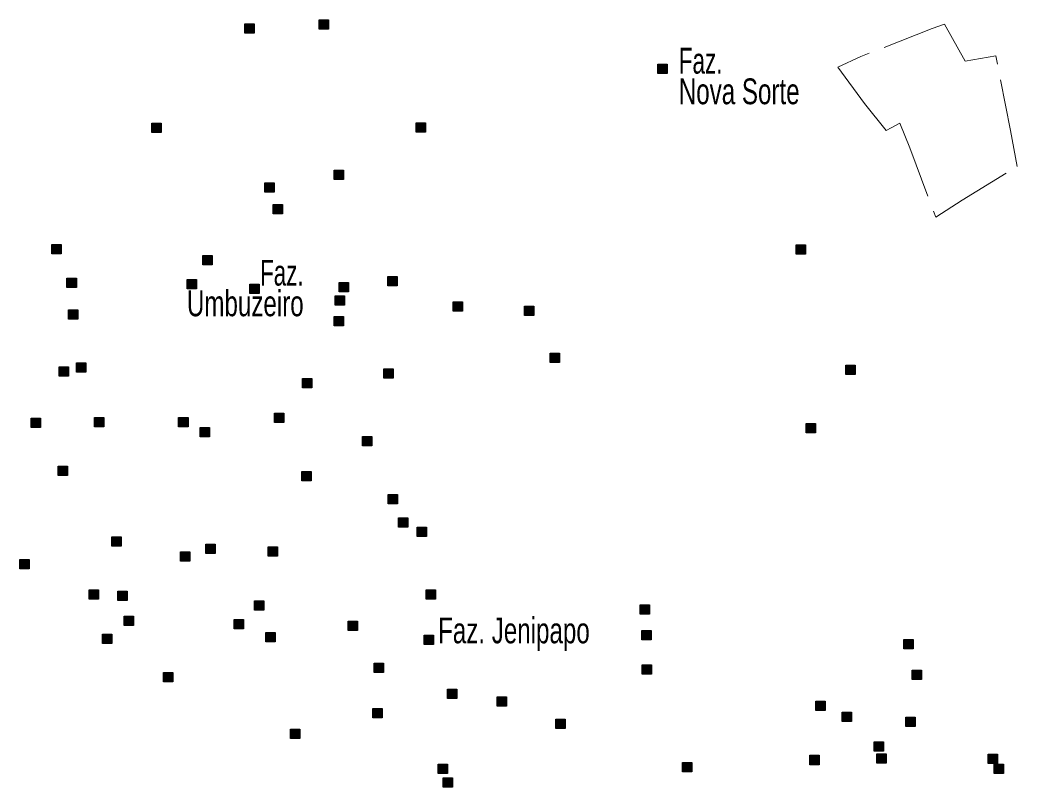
# Model space of a CAD drawing. Extents: x 445.6 to 500, y 8618.1 to 8673.4.
# Drawn here: x 463.55 to 469.73, y 8639.36 to 8644.12 of the extents above; entities that cross this region are included whole.
import ezdxf
from ezdxf.enums import TextEntityAlignment as Align

# ---------------------------------------------------------------- set-up
doc = ezdxf.new("R2010")
doc.units = 0
doc.header["$LTSCALE"] = 0.064
doc.linetypes.add('DOT_DASHED', pattern=[7.7, 5, -1.2, 0.3, -1.2])
doc.layers.add('2', color=7, linetype='Continuous', lineweight=25)
doc.layers.add('22', color=7, linetype='DOT_DASHED', lineweight=13)
doc.layers.add('61', color=7, linetype='Continuous')

msp = doc.modelspace()

# ---------------------------------------------------------------- hatches: boundary and pattern name
at = {"layer": '2'}
for points in [[(465.4002, 8644.1188), (465.4582, 8644.1188), (465.4582, 8644.0608), (465.4002, 8644.0608)], [(464.9408, 8644.0951), (464.9988, 8644.0951), (464.9988, 8644.0371), (464.9408, 8644.0371)], [(467.5005, 8643.8438), (467.5585, 8643.8438), (467.5585, 8643.7858), (467.5005, 8643.7858)], [(464.3621, 8643.4778), (464.4201, 8643.4778), (464.4201, 8643.4198), (464.3621, 8643.4198)], [(466.0028, 8643.4799), (466.0608, 8643.4799), (466.0608, 8643.4219), (466.0028, 8643.4219)], [(465.4937, 8643.1865), (465.5517, 8643.1865), (465.5517, 8643.1285), (465.4937, 8643.1285)], [(465.0647, 8643.1085), (465.1227, 8643.1085), (465.1227, 8643.0505), (465.0647, 8643.0505)], [(465.1154, 8642.973), (465.1734, 8642.973), (465.1734, 8642.915), (465.1154, 8642.915)], [(463.7423, 8642.7258), (463.8003, 8642.7258), (463.8003, 8642.6678), (463.7423, 8642.6678)], [(468.359, 8642.7224), (468.417, 8642.7224), (468.417, 8642.6644), (468.359, 8642.6644)], [(464.6796, 8642.658), (464.7376, 8642.658), (464.7376, 8642.6), (464.6796, 8642.6)], [(463.8369, 8642.5157), (463.8949, 8642.5157), (463.8949, 8642.4577), (463.8369, 8642.4577)], [(464.5817, 8642.5089), (464.6397, 8642.5089), (464.6397, 8642.4509), (464.5817, 8642.4509)], [(465.8266, 8642.5259), (465.8846, 8642.5259), (465.8846, 8642.4679), (465.8266, 8642.4679)], [(464.9701, 8642.4784), (465.0281, 8642.4784), (465.0281, 8642.4204), (464.9701, 8642.4204)], [(465.5241, 8642.4886), (465.5821, 8642.4886), (465.5821, 8642.4306), (465.5241, 8642.4306)], [(465.5004, 8642.4073), (465.5584, 8642.4073), (465.5584, 8642.3493), (465.5004, 8642.3493)], [(463.847, 8642.3192), (463.905, 8642.3192), (463.905, 8642.2612), (463.847, 8642.2612)], [(466.2319, 8642.3701), (466.2899, 8642.3701), (466.2899, 8642.3121), (466.2319, 8642.3121)], [(466.6741, 8642.3429), (466.7321, 8642.3429), (466.7321, 8642.2849), (466.6741, 8642.2849)], [(465.4937, 8642.2785), (465.5517, 8642.2785), (465.5517, 8642.2205), (465.4937, 8642.2205)], [(466.8332, 8642.0516), (466.8912, 8642.0516), (466.8912, 8641.9936), (466.8332, 8641.9936)], [(463.7889, 8641.9668), (463.8469, 8641.9668), (463.8469, 8641.9088), (463.7889, 8641.9088)], [(463.8949, 8641.9919), (463.9529, 8641.9919), (463.9529, 8641.9339), (463.8949, 8641.9339)], [(465.801, 8641.9533), (465.859, 8641.9533), (465.859, 8641.8953), (465.801, 8641.8953)], [(468.668, 8641.9775), (468.726, 8641.9775), (468.726, 8641.9195), (468.668, 8641.9195)], [(465.2966, 8641.8928), (465.3546, 8641.8928), (465.3546, 8641.8348), (465.2966, 8641.8348)], [(463.6155, 8641.648), (463.6735, 8641.648), (463.6735, 8641.59), (463.6155, 8641.59)], [(464.0079, 8641.6521), (464.0659, 8641.6521), (464.0659, 8641.5941), (464.0079, 8641.5941)], [(464.5295, 8641.6514), (464.5875, 8641.6514), (464.5875, 8641.5934), (464.5295, 8641.5934)], [(465.1243, 8641.6793), (465.1823, 8641.6793), (465.1823, 8641.6213), (465.1243, 8641.6213)], [(464.6627, 8641.5894), (464.7207, 8641.5894), (464.7207, 8641.5314), (464.6627, 8641.5314)], [(468.4214, 8641.615), (468.4794, 8641.615), (468.4794, 8641.557), (468.4214, 8641.557)], [(465.6702, 8641.5337), (465.7282, 8641.5337), (465.7282, 8641.4757), (465.6702, 8641.4757)], [(463.7812, 8641.3496), (463.8392, 8641.3496), (463.8392, 8641.2916), (463.7812, 8641.2916)], [(465.2932, 8641.3168), (465.3512, 8641.3168), (465.3512, 8641.2588), (465.2932, 8641.2588)], [(465.8288, 8641.1734), (465.8868, 8641.1734), (465.8868, 8641.1154), (465.8288, 8641.1154)], [(465.8931, 8641.0289), (465.9511, 8641.0289), (465.9511, 8640.9709), (465.8931, 8640.9709)], [(466.008, 8640.9713), (466.066, 8640.9713), (466.066, 8640.9133), (466.008, 8640.9133)], [(464.1144, 8640.9103), (464.1724, 8640.9103), (464.1724, 8640.8523), (464.1144, 8640.8523)], [(464.6987, 8640.8662), (464.7567, 8640.8662), (464.7567, 8640.8082), (464.6987, 8640.8082)], [(465.0838, 8640.8493), (465.1418, 8640.8493), (465.1418, 8640.7913), (465.0838, 8640.7913)], [(463.5451, 8640.7712), (463.6031, 8640.7712), (463.6031, 8640.7132), (463.5451, 8640.7132)], [(464.54, 8640.8188), (464.598, 8640.8188), (464.598, 8640.7608), (464.54, 8640.7608)], [(463.9741, 8640.5815), (464.0321, 8640.5815), (464.0321, 8640.5235), (463.9741, 8640.5235)], [(466.0654, 8640.5817), (466.1234, 8640.5817), (466.1234, 8640.5237), (466.0654, 8640.5237)], [(464.1515, 8640.5749), (464.2095, 8640.5749), (464.2095, 8640.5169), (464.1515, 8640.5169)], [(464.9993, 8640.5139), (465.0573, 8640.5139), (465.0573, 8640.4559), (464.9993, 8640.4559)], [(467.3912, 8640.4902), (467.4492, 8640.4902), (467.4492, 8640.4322), (467.3912, 8640.4322)], [(464.1921, 8640.419), (464.2501, 8640.419), (464.2501, 8640.361), (464.1921, 8640.361)], [(464.8744, 8640.3987), (464.9324, 8640.3987), (464.9324, 8640.3407), (464.8744, 8640.3407)], [(465.5803, 8640.3886), (465.6383, 8640.3886), (465.6383, 8640.3306), (465.5803, 8640.3306)], [(464.057, 8640.3072), (464.115, 8640.3072), (464.115, 8640.2492), (464.057, 8640.2492)], [(465.0703, 8640.3174), (465.1283, 8640.3174), (465.1283, 8640.2594), (465.0703, 8640.2594)], [(466.0519, 8640.3005), (466.1099, 8640.3005), (466.1099, 8640.2425), (466.0519, 8640.2425)], [(467.4014, 8640.331), (467.4594, 8640.331), (467.4594, 8640.273), (467.4014, 8640.273)], [(469.027, 8640.2735), (469.085, 8640.2735), (469.085, 8640.2155), (469.027, 8640.2155)], [(465.7411, 8640.1277), (465.7991, 8640.1277), (465.7991, 8640.0697), (465.7411, 8640.0697)], [(467.4047, 8640.1175), (467.4627, 8640.1175), (467.4627, 8640.0595), (467.4047, 8640.0595)], [(464.4353, 8640.0701), (464.4933, 8640.0701), (464.4933, 8640.0121), (464.4353, 8640.0121)], [(469.079, 8640.0846), (469.137, 8640.0846), (469.137, 8640.0266), (469.079, 8640.0266)], [(466.1967, 8639.9652), (466.2547, 8639.9652), (466.2547, 8639.9072), (466.1967, 8639.9072)], [(466.5041, 8639.9178), (466.5621, 8639.9178), (466.5621, 8639.8598), (466.5041, 8639.8598)], [(465.7339, 8639.8467), (465.7919, 8639.8467), (465.7919, 8639.7887), (465.7339, 8639.7887)], [(468.4818, 8639.8908), (468.5398, 8639.8908), (468.5398, 8639.8328), (468.4818, 8639.8328)], [(466.8688, 8639.7789), (466.9268, 8639.7789), (466.9268, 8639.7209), (466.8688, 8639.7209)], [(468.644, 8639.8231), (468.702, 8639.8231), (468.702, 8639.7651), (468.644, 8639.7651)], [(469.0403, 8639.7925), (469.0983, 8639.7925), (469.0983, 8639.7345), (469.0403, 8639.7345)], [(465.2233, 8639.718), (465.2813, 8639.718), (465.2813, 8639.66), (465.2233, 8639.66)], [(468.8433, 8639.6401), (468.9013, 8639.6401), (468.9013, 8639.5821), (468.8433, 8639.5821)], [(468.4447, 8639.5554), (468.5027, 8639.5554), (468.5027, 8639.4974), (468.4447, 8639.4974)], [(468.8601, 8639.5656), (468.9181, 8639.5656), (468.9181, 8639.5076), (468.8601, 8639.5076)], [(469.5498, 8639.5619), (469.6078, 8639.5619), (469.6078, 8639.5039), (469.5498, 8639.5039)], [(466.1393, 8639.5011), (466.1973, 8639.5011), (466.1973, 8639.4431), (466.1393, 8639.4431)], [(467.655, 8639.511), (467.713, 8639.511), (467.713, 8639.453), (467.655, 8639.453)], [(469.587, 8639.5008), (469.645, 8639.5008), (469.645, 8639.4428), (469.587, 8639.4428)], [(466.1697, 8639.4164), (466.2277, 8639.4164), (466.2277, 8639.3584), (466.1697, 8639.3584)]]:
    msp.add_hatch(color=256, dxfattribs=at).paths.add_polyline_path(points)

# ---------------------------------------------------------------- linework, layer by layer
for points in [[(465.4002, 8644.1188), (465.4582, 8644.1188), (465.4582, 8644.0608), (465.4002, 8644.0608)], [(464.9408, 8644.0951), (464.9988, 8644.0951), (464.9988, 8644.0371), (464.9408, 8644.0371)], [(467.5005, 8643.8438), (467.5585, 8643.8438), (467.5585, 8643.7858), (467.5005, 8643.7858)], [(464.3621, 8643.4778), (464.4201, 8643.4778), (464.4201, 8643.4198), (464.3621, 8643.4198)], [(466.0028, 8643.4799), (466.0608, 8643.4799), (466.0608, 8643.4219), (466.0028, 8643.4219)], [(465.4937, 8643.1865), (465.5517, 8643.1865), (465.5517, 8643.1285), (465.4937, 8643.1285)], [(465.0647, 8643.1085), (465.1227, 8643.1085), (465.1227, 8643.0505), (465.0647, 8643.0505)], [(465.1154, 8642.973), (465.1734, 8642.973), (465.1734, 8642.915), (465.1154, 8642.915)], [(463.7423, 8642.7258), (463.8003, 8642.7258), (463.8003, 8642.6678), (463.7423, 8642.6678)], [(468.359, 8642.7224), (468.417, 8642.7224), (468.417, 8642.6644), (468.359, 8642.6644)], [(464.6796, 8642.658), (464.7376, 8642.658), (464.7376, 8642.6), (464.6796, 8642.6)], [(463.8369, 8642.5157), (463.8949, 8642.5157), (463.8949, 8642.4577), (463.8369, 8642.4577)], [(464.5817, 8642.5089), (464.6397, 8642.5089), (464.6397, 8642.4509), (464.5817, 8642.4509)], [(465.8266, 8642.5259), (465.8846, 8642.5259), (465.8846, 8642.4679), (465.8266, 8642.4679)], [(464.9701, 8642.4784), (465.0281, 8642.4784), (465.0281, 8642.4204), (464.9701, 8642.4204)], [(465.5241, 8642.4886), (465.5821, 8642.4886), (465.5821, 8642.4306), (465.5241, 8642.4306)], [(465.5004, 8642.4073), (465.5584, 8642.4073), (465.5584, 8642.3493), (465.5004, 8642.3493)], [(463.847, 8642.3192), (463.905, 8642.3192), (463.905, 8642.2612), (463.847, 8642.2612)], [(466.2319, 8642.3701), (466.2899, 8642.3701), (466.2899, 8642.3121), (466.2319, 8642.3121)], [(466.6741, 8642.3429), (466.7321, 8642.3429), (466.7321, 8642.2849), (466.6741, 8642.2849)], [(465.4937, 8642.2785), (465.5517, 8642.2785), (465.5517, 8642.2205), (465.4937, 8642.2205)], [(466.8332, 8642.0516), (466.8912, 8642.0516), (466.8912, 8641.9936), (466.8332, 8641.9936)], [(463.7889, 8641.9668), (463.8469, 8641.9668), (463.8469, 8641.9088), (463.7889, 8641.9088)], [(463.8949, 8641.9919), (463.9529, 8641.9919), (463.9529, 8641.9339), (463.8949, 8641.9339)], [(465.801, 8641.9533), (465.859, 8641.9533), (465.859, 8641.8953), (465.801, 8641.8953)], [(468.668, 8641.9775), (468.726, 8641.9775), (468.726, 8641.9195), (468.668, 8641.9195)], [(465.2966, 8641.8928), (465.3546, 8641.8928), (465.3546, 8641.8348), (465.2966, 8641.8348)], [(463.6155, 8641.648), (463.6735, 8641.648), (463.6735, 8641.59), (463.6155, 8641.59)], [(464.0079, 8641.6521), (464.0659, 8641.6521), (464.0659, 8641.5941), (464.0079, 8641.5941)], [(464.5295, 8641.6514), (464.5875, 8641.6514), (464.5875, 8641.5934), (464.5295, 8641.5934)], [(465.1243, 8641.6793), (465.1823, 8641.6793), (465.1823, 8641.6213), (465.1243, 8641.6213)], [(464.6627, 8641.5894), (464.7207, 8641.5894), (464.7207, 8641.5314), (464.6627, 8641.5314)], [(468.4214, 8641.615), (468.4794, 8641.615), (468.4794, 8641.557), (468.4214, 8641.557)], [(465.6702, 8641.5337), (465.7282, 8641.5337), (465.7282, 8641.4757), (465.6702, 8641.4757)], [(463.7812, 8641.3496), (463.8392, 8641.3496), (463.8392, 8641.2916), (463.7812, 8641.2916)], [(465.2932, 8641.3168), (465.3512, 8641.3168), (465.3512, 8641.2588), (465.2932, 8641.2588)], [(465.8288, 8641.1734), (465.8868, 8641.1734), (465.8868, 8641.1154), (465.8288, 8641.1154)], [(465.8931, 8641.0289), (465.9511, 8641.0289), (465.9511, 8640.9709), (465.8931, 8640.9709)], [(466.008, 8640.9713), (466.066, 8640.9713), (466.066, 8640.9133), (466.008, 8640.9133)], [(464.1144, 8640.9103), (464.1724, 8640.9103), (464.1724, 8640.8523), (464.1144, 8640.8523)], [(464.6987, 8640.8662), (464.7567, 8640.8662), (464.7567, 8640.8082), (464.6987, 8640.8082)], [(465.0838, 8640.8493), (465.1418, 8640.8493), (465.1418, 8640.7913), (465.0838, 8640.7913)], [(463.5451, 8640.7712), (463.6031, 8640.7712), (463.6031, 8640.7132), (463.5451, 8640.7132)], [(464.54, 8640.8188), (464.598, 8640.8188), (464.598, 8640.7608), (464.54, 8640.7608)], [(463.9741, 8640.5815), (464.0321, 8640.5815), (464.0321, 8640.5235), (463.9741, 8640.5235)], [(466.0654, 8640.5817), (466.1234, 8640.5817), (466.1234, 8640.5237), (466.0654, 8640.5237)], [(464.1515, 8640.5749), (464.2095, 8640.5749), (464.2095, 8640.5169), (464.1515, 8640.5169)], [(464.9993, 8640.5139), (465.0573, 8640.5139), (465.0573, 8640.4559), (464.9993, 8640.4559)], [(467.3912, 8640.4902), (467.4492, 8640.4902), (467.4492, 8640.4322), (467.3912, 8640.4322)], [(464.1921, 8640.419), (464.2501, 8640.419), (464.2501, 8640.361), (464.1921, 8640.361)], [(464.8744, 8640.3987), (464.9324, 8640.3987), (464.9324, 8640.3407), (464.8744, 8640.3407)], [(465.5803, 8640.3886), (465.6383, 8640.3886), (465.6383, 8640.3306), (465.5803, 8640.3306)], [(464.057, 8640.3072), (464.115, 8640.3072), (464.115, 8640.2492), (464.057, 8640.2492)], [(465.0703, 8640.3174), (465.1283, 8640.3174), (465.1283, 8640.2594), (465.0703, 8640.2594)], [(466.0519, 8640.3005), (466.1099, 8640.3005), (466.1099, 8640.2425), (466.0519, 8640.2425)], [(467.4014, 8640.331), (467.4594, 8640.331), (467.4594, 8640.273), (467.4014, 8640.273)], [(469.027, 8640.2735), (469.085, 8640.2735), (469.085, 8640.2155), (469.027, 8640.2155)], [(465.7411, 8640.1277), (465.7991, 8640.1277), (465.7991, 8640.0697), (465.7411, 8640.0697)], [(467.4047, 8640.1175), (467.4627, 8640.1175), (467.4627, 8640.0595), (467.4047, 8640.0595)], [(464.4353, 8640.0701), (464.4933, 8640.0701), (464.4933, 8640.0121), (464.4353, 8640.0121)], [(469.079, 8640.0846), (469.137, 8640.0846), (469.137, 8640.0266), (469.079, 8640.0266)], [(466.1967, 8639.9652), (466.2547, 8639.9652), (466.2547, 8639.9072), (466.1967, 8639.9072)], [(466.5041, 8639.9178), (466.5621, 8639.9178), (466.5621, 8639.8598), (466.5041, 8639.8598)], [(465.7339, 8639.8467), (465.7919, 8639.8467), (465.7919, 8639.7887), (465.7339, 8639.7887)], [(468.4818, 8639.8908), (468.5398, 8639.8908), (468.5398, 8639.8328), (468.4818, 8639.8328)], [(466.8688, 8639.7789), (466.9268, 8639.7789), (466.9268, 8639.7209), (466.8688, 8639.7209)], [(468.644, 8639.8231), (468.702, 8639.8231), (468.702, 8639.7651), (468.644, 8639.7651)], [(469.0403, 8639.7925), (469.0983, 8639.7925), (469.0983, 8639.7345), (469.0403, 8639.7345)], [(465.2233, 8639.718), (465.2813, 8639.718), (465.2813, 8639.66), (465.2233, 8639.66)], [(468.8433, 8639.6401), (468.9013, 8639.6401), (468.9013, 8639.5821), (468.8433, 8639.5821)], [(468.4447, 8639.5554), (468.5027, 8639.5554), (468.5027, 8639.4974), (468.4447, 8639.4974)], [(468.8601, 8639.5656), (468.9181, 8639.5656), (468.9181, 8639.5076), (468.8601, 8639.5076)], [(469.5498, 8639.5619), (469.6078, 8639.5619), (469.6078, 8639.5039), (469.5498, 8639.5039)], [(466.1393, 8639.5011), (466.1973, 8639.5011), (466.1973, 8639.4431), (466.1393, 8639.4431)], [(467.655, 8639.511), (467.713, 8639.511), (467.713, 8639.453), (467.655, 8639.453)], [(469.587, 8639.5008), (469.645, 8639.5008), (469.645, 8639.4428), (469.587, 8639.4428)], [(466.1697, 8639.4164), (466.2277, 8639.4164), (466.2277, 8639.3584), (466.1697, 8639.3584)]]:
    msp.add_lwpolyline(points, close=True, dxfattribs=at)
at = {"layer": '22'}
msp.add_lwpolyline([(468.9478, 8643.4493), (469.0026, 8643.4785), (469.0647, 8643.3253), (469.2254, 8642.895), (469.3897, 8643.0007), (469.7294, 8643.2086), (469.689, 8643.4331), (469.5977, 8643.8963), (469.4078, 8643.8634), (469.2799, 8644.0932), (469.2025, 8644.0663), (468.7605, 8643.8913), (468.6181, 8643.8256), (468.7824, 8643.5995), (468.9176, 8643.4317)], close=True, dxfattribs=at)

# ---------------------------------------------------------------- texts
at = {"layer": '61'}
for s, width, p in [('Faz.', 0.65, (467.6315, 8643.7857)), ('Nova Sorte', 0.7, (467.6315, 8643.5957)), ('Faz. Jenipapo', 0.7, (466.1384, 8640.2505))]:
    msp.add_text(s, height=0.16, dxfattribs=dict(at, width=width)).set_placement(p)
for s, width, p in [('Faz.', 0.65, (465.3048, 8642.4701)), ('Umbuzeiro', 0.7, (465.3048, 8642.2801))]:
    msp.add_text(s, height=0.16, dxfattribs=dict(at, width=width)).set_placement(p, align=Align.RIGHT)

doc.saveas('drawing.dxf')
